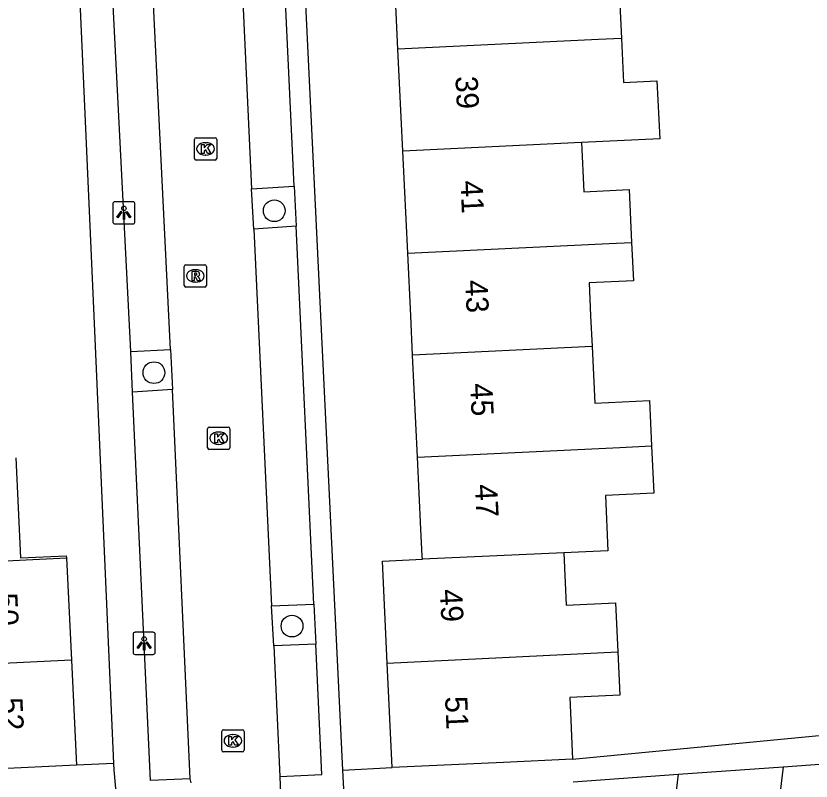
# Model space of a CAD drawing. Extents: x 162250 to 162654, y 380744 to 381605.
# Drawn here: x 162393.23 to 162428.97, y 380979.08 to 381013.48 of the extents above; entities that cross this region are included whole.
import ezdxf

# ---------------------------------------------------------------- set-up
doc = ezdxf.new("R2010")
doc.units = 0
for name, color, linetype in [('IMGEO_Boom', 7, 'Continuous'), ('IMGEO_Kolk', 7, 'Continuous'), ('IMGEO_Lichtpunt', 7, 'Continuous'), ('IMGEO_Pand', 7, 'Continuous'), ('IMGEO_Pand_nummerreeks', 7, 'Continuous'), ('IMGEO_Parkeervlak_open', 7, 'Continuous'), ('IMGEO_Rijbaan_lokaal_open', 7, 'Continuous'), ('IMGEO_Rioolput', 7, 'Continuous'), ('IMGEO_Voetpad_open', 7, 'Continuous')]:
    doc.layers.add(name, color=color, linetype=linetype)

msp = doc.modelspace()

# ---------------------------------------------------------------- linework, layer by layer
at = {"layer": 'IMGEO_Boom'}
for centre in [(162404.844, 381004.72), (162399.436, 380997.439), (162405.641, 380986.046)]:
    msp.add_circle(centre, 0.489, dxfattribs=at)
at = {"layer": 'IMGEO_Kolk'}
for p, q in [((162401.254, 381007.072), (162401.254, 381007.924)), ((162401.329, 381007.998), (162402.181, 381007.998)), ((162401.742, 381007.778), (162401.767, 381007.778)), ((162402.255, 381007.924), (162402.255, 381007.072)), ((162402.181, 381006.998), (162401.329, 381006.998)), ((162401.765, 381007.218), (162401.74, 381007.218)), ((162401.846, 380994.066), (162401.846, 380994.918)), ((162401.921, 380994.992), (162402.773, 380994.992)), ((162402.847, 380994.918), (162402.847, 380994.066)), ((162402.334, 380994.772), (162402.359, 380994.772)), ((162402.357, 380994.212), (162402.332, 380994.212)), ((162402.773, 380993.992), (162401.921, 380993.992)), ((162402.484, 380980.463), (162402.484, 380981.315)), ((162402.559, 380981.389), (162403.411, 380981.389)), ((162403.485, 380981.315), (162403.485, 380980.463)), ((162402.972, 380981.169), (162402.997, 380981.169)), ((162402.995, 380980.609), (162402.97, 380980.609)), ((162403.411, 380980.389), (162402.559, 380980.389))]:
    msp.add_line(p, q, dxfattribs=at)
for points in [[(162401.254, 381007.072), (162401.254, 381007.924)], [(162401.329, 381007.998), (162402.181, 381007.998)], [(162401.575, 381007.698), (162401.698, 381007.698), (162401.698, 381007.547), (162401.828, 381007.698), (162401.992, 381007.698), (162401.846, 381007.547), (162401.999, 381007.298), (162401.847, 381007.298), (162401.762, 381007.462), (162401.698, 381007.395), (162401.698, 381007.298), (162401.575, 381007.298), (162401.575, 381007.698)], [(162402.255, 381007.924), (162402.255, 381007.072)], [(162402.181, 381006.998), (162401.329, 381006.998)], [(162401.846, 380994.066), (162401.846, 380994.918)], [(162401.921, 380994.992), (162402.773, 380994.992)], [(162402.847, 380994.918), (162402.847, 380994.066)], [(162402.167, 380994.692), (162402.29, 380994.692), (162402.29, 380994.541), (162402.42, 380994.692), (162402.584, 380994.692), (162402.438, 380994.541), (162402.591, 380994.292), (162402.439, 380994.292), (162402.354, 380994.456), (162402.29, 380994.389), (162402.29, 380994.292), (162402.167, 380994.292), (162402.167, 380994.692)], [(162402.773, 380993.992), (162401.921, 380993.992)], [(162402.484, 380980.463), (162402.484, 380981.315)], [(162402.559, 380981.389), (162403.411, 380981.389)], [(162403.485, 380981.315), (162403.485, 380980.463)], [(162402.805, 380981.089), (162402.928, 380981.089), (162402.928, 380980.938), (162403.058, 380981.089), (162403.222, 380981.089), (162403.076, 380980.938), (162403.229, 380980.689), (162403.077, 380980.689), (162402.992, 380980.853), (162402.928, 380980.786), (162402.928, 380980.689), (162402.805, 380980.689), (162402.805, 380981.089)], [(162403.411, 380980.389), (162402.559, 380980.389)]]:
    msp.add_lwpolyline(points, dxfattribs=at)
for centre, start, end in [((162401.331, 381007.922), 91.552, 178.448), ((162401.331, 381007.922), 91.552, 178.448), ((162402.179, 381007.922), 1.552, 88.448), ((162402.179, 381007.922), 1.552, 88.448), ((162401.331, 381007.074), 181.552, 268.448), ((162401.331, 381007.074), 181.552, 268.448), ((162402.179, 381007.074), 271.552, 358.448), ((162402.179, 381007.074), 271.552, 358.448), ((162401.923, 380994.916), 91.552, 178.448), ((162401.923, 380994.916), 91.552, 178.448), ((162402.771, 380994.916), 1.552, 88.448), ((162402.771, 380994.916), 1.552, 88.448), ((162401.923, 380994.068), 181.552, 268.448), ((162401.923, 380994.068), 181.552, 268.448), ((162402.771, 380994.068), 271.552, 358.448), ((162402.771, 380994.068), 271.552, 358.448), ((162402.561, 380981.313), 91.552, 178.448), ((162402.561, 380981.313), 91.552, 178.448), ((162403.409, 380981.313), 1.552, 88.448), ((162403.409, 380981.313), 1.552, 88.448), ((162402.561, 380980.465), 181.552, 268.448), ((162402.561, 380980.465), 181.552, 268.448), ((162403.409, 380980.465), 271.552, 358.448), ((162403.409, 380980.465), 271.552, 358.448)]:
    msp.add_arc(centre, 0.0765, start, end, dxfattribs=at)
for centre, major_axis, ratio, start_param, end_param in [((162401.741, 381007.498), (-0.387, 0.002), 0.722429, 4.712389, 7.853982), ((162401.766, 381007.498), (-0.39, 0.002), 0.717154, 1.570796, 4.712389), ((162402.333, 380994.492), (-0.387, 0.002), 0.722429, 4.712389, 7.853982), ((162402.358, 380994.492), (-0.39, 0.002), 0.717154, 1.570796, 4.712389), ((162402.971, 380980.889), (-0.387, 0.002), 0.722429, 4.712389, 7.853982), ((162402.996, 380980.889), (-0.39, 0.002), 0.717154, 1.570796, 4.712389)]:
    msp.add_ellipse(centre, major_axis=major_axis, ratio=ratio, start_param=start_param, end_param=end_param, dxfattribs=at)
at = {"layer": 'IMGEO_Lichtpunt'}
for p, q in [((162397.585, 381005.028), (162397.585, 381004.221)), ((162397.585, 381005.028), (162397.585, 381004.221)), ((162398.487, 381005.123), (162397.679, 381005.123)), ((162398.487, 381005.123), (162397.679, 381005.123)), ((162398.581, 381004.221), (162398.581, 381005.028)), ((162398.581, 381004.221), (162398.581, 381005.028)), ((162397.679, 381004.127), (162398.487, 381004.127)), ((162397.679, 381004.127), (162398.487, 381004.127)), ((162398.496, 380985.671), (162398.496, 380984.864)), ((162398.496, 380985.671), (162398.496, 380984.864)), ((162399.398, 380985.766), (162398.59, 380985.766)), ((162399.398, 380985.766), (162398.59, 380985.766)), ((162399.492, 380984.864), (162399.492, 380985.671)), ((162399.492, 380984.864), (162399.492, 380985.671)), ((162398.59, 380984.77), (162399.398, 380984.77)), ((162398.59, 380984.77), (162399.398, 380984.77))]:
    msp.add_line(p, q, dxfattribs=at)
for points in [[(162397.959, 381004.692), (162397.998, 381004.664), (162397.81, 381004.402), (162397.772, 381004.429), (162397.959, 381004.692)], [(162398.061, 381004.644), (162398.108, 381004.644), (162398.108, 381004.322), (162398.061, 381004.322), (162398.061, 381004.644)], [(162398.171, 381004.664), (162398.209, 381004.691), (162398.396, 381004.429), (162398.357, 381004.401), (162398.171, 381004.664)], [(162398.87, 380985.335), (162398.909, 380985.307), (162398.721, 380985.045), (162398.683, 380985.072), (162398.87, 380985.335)], [(162398.972, 380985.287), (162399.019, 380985.287), (162399.019, 380984.965), (162398.972, 380984.965), (162398.972, 380985.287)], [(162399.082, 380985.307), (162399.12, 380985.334), (162399.307, 380985.072), (162399.268, 380985.044), (162399.082, 380985.307)]]:
    msp.add_lwpolyline(points, dxfattribs=at)
for centre in [(162398.084, 381004.826), (162398.995, 380985.469)]:
    msp.add_circle(centre, 0.0994, dxfattribs=at)
for centre, start, end in [((162397.679, 381005.028), 90, 180), ((162397.679, 381005.028), 90, 180), ((162398.487, 381005.028), 0, 90), ((162398.487, 381005.028), 0, 90), ((162397.679, 381004.221), 180, 270), ((162397.679, 381004.221), 180, 270), ((162398.487, 381004.221), 270, 0), ((162398.487, 381004.221), 270, 360), ((162398.59, 380985.671), 90, 180), ((162398.59, 380985.671), 90, 180), ((162399.398, 380985.671), 0, 90), ((162399.398, 380985.671), 0, 90), ((162398.59, 380984.864), 180, 270), ((162398.59, 380984.864), 180, 270), ((162399.398, 380984.864), 270, 0), ((162399.398, 380984.864), 270, 360)]:
    msp.add_arc(centre, 0.0946, start, end, dxfattribs=at)
at = {"layer": 'IMGEO_Pand'}
for points in [[(162418.219, 381016.955), (162418.336, 381014.524), (162420.345, 381014.621), (162420.449, 381012.467)], [(162410.401, 381011.985), (162410.182, 381016.57)], [(162420.449, 381012.467), (162419.413, 381012.417), (162410.401, 381011.985)], [(162420.449, 381012.467), (162420.544, 381010.489), (162422.042, 381010.561), (162422.167, 381007.953), (162418.647, 381007.784)], [(162410.621, 381007.399), (162410.401, 381011.985)], [(162418.647, 381007.784), (162410.621, 381007.399)], [(162418.647, 381007.784), (162418.753, 381005.575), (162420.794, 381005.673), (162420.908, 381003.297)], [(162410.841, 381002.814), (162410.621, 381007.399)], [(162410.841, 381002.814), (162419.893, 381003.248), (162420.908, 381003.297)], [(162420.908, 381003.297), (162420.991, 381001.574), (162418.994, 381001.478), (162419.064, 381000), (162419.13, 380998.615)], [(162411.061, 380998.228), (162410.976, 381000), (162410.841, 381002.814)], [(162419.13, 380998.615), (162411.061, 380998.228)], [(162419.13, 380998.615), (162419.252, 380996.066), (162421.705, 380996.183), (162421.802, 380994.147)], [(162411.281, 380993.643), (162411.061, 380998.228)], [(162411.281, 380993.643), (162420.372, 380994.079), (162421.802, 380994.147)], [(162421.802, 380994.147), (162421.903, 380992.016), (162419.725, 380991.913), (162419.843, 380989.435), (162417.855, 380989.341)], [(162393.22, 380993.608), (162393.439, 380989.11), (162395.493, 380989.21), (162395.498, 380989.11)], [(162411.5, 380989.052), (162411.494, 380989.187), (162411.436, 380990.408), (162411.281, 380993.643)], [(162387.339, 380988.713), (162395.498, 380989.11)], [(162395.498, 380989.11), (162395.722, 380984.512)], [(162417.855, 380989.341), (162411.5, 380989.052)], [(162417.855, 380989.341), (162417.967, 380986.989), (162420.176, 380987.094), (162420.281, 380984.882)], [(162409.923, 380984.385), (162409.705, 380988.971), (162411.5, 380989.052)], [(162409.923, 380984.385), (162420.281, 380984.882)], [(162420.281, 380984.882), (162420.373, 380982.94), (162418.124, 380982.833), (162418.255, 380980.069)], [(162395.722, 380984.512), (162387.397, 380984.107), (162385.685, 380984.024)], [(162395.722, 380984.512), (162395.952, 380979.795)], [(162410.146, 380979.684), (162409.923, 380984.385)], [(162395.952, 380979.795), (162390.958, 380979.552), (162387.833, 380979.4)], [(162418.255, 380980.069), (162415.141, 380979.921), (162410.146, 380979.684)], [(162427.723, 380979.725), (162432.442, 380980.066)], [(162423.004, 380979.385), (162427.723, 380979.725)], [(162427.723, 380979.725), (162427.407, 380977.1)], [(162418.285, 380979.044), (162423.004, 380979.385)], [(162423.004, 380979.385), (162422.688, 380976.759)]]:
    msp.add_lwpolyline(points, dxfattribs=at)
at = {"layer": 'IMGEO_Parkeervlak_open'}
for points in [[(162403.827, 381005.703), (162405.739, 381005.822)], [(162405.823, 381004.021), (162403.924, 381003.896)], [(162398.395, 380998.385), (162400.183, 380998.483)], [(162400.263, 380996.681), (162398.465, 380996.566)], [(162404.724, 380986.959), (162406.625, 380987.038)], [(162406.715, 380985.239), (162404.818, 380985.162)]]:
    msp.add_lwpolyline(points, dxfattribs=at)
at = {"layer": 'IMGEO_Rijbaan_lokaal_open'}
for points in [[(162403.025, 381022.884), (162403.827, 381005.703)], [(162400.183, 380998.483), (162399.335, 381015.527)], [(162403.924, 381003.896), (162403.827, 381005.703)], [(162403.924, 381003.896), (162404.724, 380986.959)], [(162400.183, 380998.483), (162400.263, 380996.681)], [(162401.058, 380979.183), (162400.263, 380996.681)], [(162404.818, 380985.162), (162404.724, 380986.959)], [(162404.818, 380985.162), (162405.089, 380979.278)], [(162401.105, 380979.006), (162401.058, 380979.183)], [(162405.089, 380979.278), (162405.144, 380978.079)]]:
    msp.add_lwpolyline(points, dxfattribs=at)
at = {"layer": 'IMGEO_Rioolput'}
for p, q in [((162400.794, 381001.362), (162400.794, 381002.214)), ((162400.869, 381002.288), (162401.721, 381002.288)), ((162401.282, 381002.068), (162401.307, 381002.068)), ((162401.795, 381002.214), (162401.795, 381001.362)), ((162401.721, 381001.288), (162400.869, 381001.288)), ((162401.305, 381001.508), (162401.28, 381001.508))]:
    msp.add_line(p, q, dxfattribs=at)
for points in [[(162400.794, 381001.362), (162400.794, 381002.214)], [(162400.869, 381002.288), (162401.721, 381002.288)], [(162401.383, 381001.986), (162401.131, 381001.988), (162401.131, 381001.588)], [(162401.795, 381002.214), (162401.795, 381001.362)], [(162401.131, 381001.588), (162401.255, 381001.588), (162401.255, 381001.75), (162401.266, 381001.75)], [(162401.309, 381001.907), (162401.255, 381001.907), (162401.255, 381001.826)], [(162401.255, 381001.826), (162401.307, 381001.826)], [(162401.313, 381001.721), (162401.384, 381001.588), (162401.524, 381001.588), (162401.459, 381001.714)], [(162401.721, 381001.288), (162400.869, 381001.288)]]:
    msp.add_lwpolyline(points, dxfattribs=at)
for centre, radius, start, end in [((162400.871, 381002.212), 0.0765, 91.552, 178.448), ((162400.871, 381002.212), 0.0765, 91.552, 178.448), ((162401.382, 381001.876), 0.109, 350.3612, 89.416), ((162401.719, 381002.212), 0.0765, 1.552, 88.448), ((162401.719, 381002.212), 0.0765, 1.552, 88.448), ((162401.265, 381001.697), 0.0533, 26.0293, 88.6989), ((162401.291, 381002.015), 0.19, 274.7715, 282.9687), ((162401.315, 381001.811), 0.0964, 77.0061, 93.1865), ((162401.329, 381001.868), 0.0378, 276.6634, 79.6772), ((162401.38, 381001.876), 0.112, 277.5842, 350.9817), ((162401.364, 381001.661), 0.108, 29.5134, 73.7905), ((162400.871, 381001.364), 0.0765, 181.552, 268.448), ((162400.871, 381001.364), 0.0765, 181.552, 268.448), ((162401.719, 381001.364), 0.0765, 271.552, 358.448), ((162401.719, 381001.364), 0.0765, 271.552, 358.448)]:
    msp.add_arc(centre, radius, start, end, dxfattribs=at)
for centre, major_axis, ratio, start_param, end_param in [((162401.281, 381001.788), (-0.387, 0.002), 0.722429, 4.712389, 7.853982), ((162401.306, 381001.788), (-0.39, 0.002), 0.717154, 1.570796, 4.712389)]:
    msp.add_ellipse(centre, major_axis=major_axis, ratio=ratio, start_param=start_param, end_param=end_param, dxfattribs=at)
at = {"layer": 'IMGEO_Voetpad_open'}
for points in [[(162397.638, 380979.87), (162396.746, 381000), (162395.762, 381022.213), (162394.094, 381022.237), (162392.384, 381062.316), (162393.904, 381062.404), (162392.344, 381095.083)], [(162402.365, 381094.66), (162406.928, 381000), (162407.912, 380979.576)], [(162405.739, 381005.822), (162404.924, 381023.052), (162405.007, 381028.026), (162404.923, 381029.732)], [(162398.395, 380998.385), (162397.528, 381015.45)], [(162405.739, 381005.822), (162405.823, 381004.021)], [(162406.625, 380987.038), (162405.823, 381004.021)], [(162398.465, 380996.566), (162398.395, 380998.385)], [(162401.058, 380979.183), (162399.274, 380979.112), (162398.465, 380996.566)], [(162406.625, 380987.038), (162406.715, 380985.239)], [(162405.089, 380979.278), (162406.983, 380979.381), (162406.715, 380985.239)], [(162418.255, 380980.069), (162433.083, 380981.486)], [(162397.638, 380979.87), (162395.952, 380979.795)], [(162396.071, 380978.402), (162397.763, 380978.23), (162397.651, 380979.588), (162397.638, 380979.87)], [(162407.912, 380979.576), (162410.146, 380979.684)], [(162407.912, 380979.576), (162407.968, 380978.425)]]:
    msp.add_lwpolyline(points, dxfattribs=at)

# ---------------------------------------------------------------- texts
at = {"layer": 'IMGEO_Pand_nummerreeks'}
for s, rotation, p in [('39', 272.7446, (162412.983, 381010.753)), ('41', 272.7446, (162413.208, 381006.058)), ('43', 272.7446, (162413.423, 381001.588)), ('45', 272.7427, (162413.645, 380996.946)), ('47', 272.7443, (162413.863, 380992.403)), ('49', 272.7156, (162412.288, 380987.692)), ('50', 272.7911, (162392.292, 380987.519)), ('52', 272.7911, (162392.521, 380982.818)), ('51', 272.7173, (162412.517, 380982.871))]:
    msp.add_text(s, height=1, rotation=rotation, dxfattribs=at).set_placement(p)

doc.saveas('drawing.dxf')
